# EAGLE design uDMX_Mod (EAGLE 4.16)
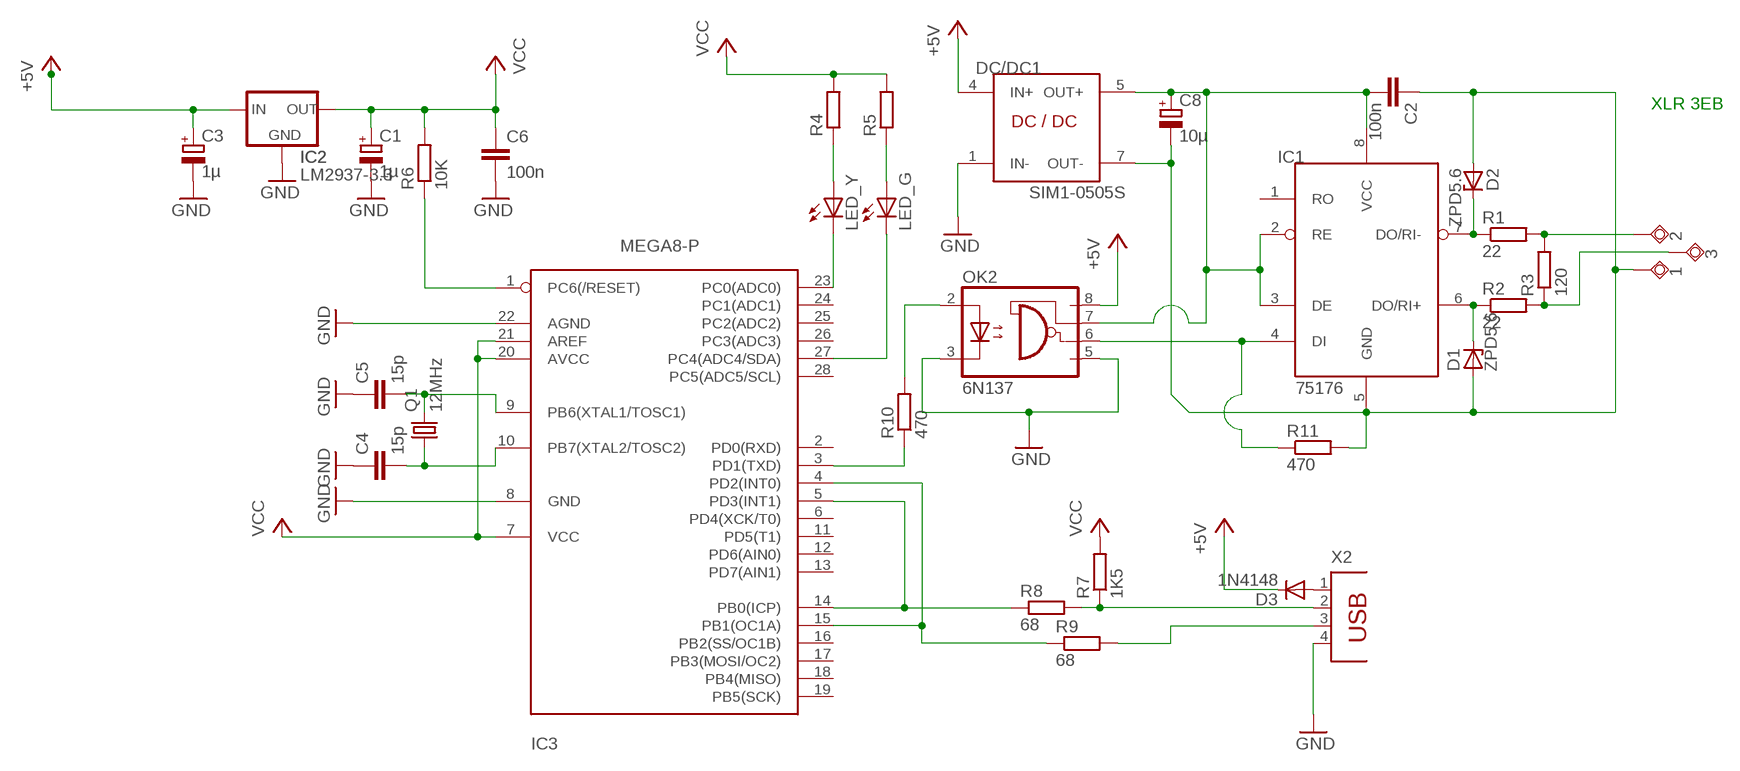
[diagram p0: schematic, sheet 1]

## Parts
1  PAD  [PAD]
2  PAD  [PAD]
3  PAD  [PAD]
C1  1µ  CPOL-EUE2.5-5  [E2,5-5]
C2  100n  C2.5/4  [C2.5-4]
C3  1µ  CPOL-EUE2.5-5  [E2,5-5]
C4  15p  C2.5/4  [C2.5-4]
C5  15p  C2.5/4  [C2.5-4]
C6  100n  C2.5/4  [C2.5-4]
C8  10µ  CPOL-EUE2.5-5  [E2,5-5]
D1  ZPD5.6  ZPD  [DO35Z10]
D2  ZPD5.6  ZPD  [DO35Z10]
D3  1N4148  [DO35-10]
DC/DC1  SIM1-0505S  [DIL08]
IC1  75176  [DIL08]
IC2  LM2937-3.3  LM2937  [TO220S]
IC3  MEGA8-P  [DIL28-3]
LED_G  LED3MM  [LED3MM]
LED_Y  LED3MM  [LED3MM]
OK2  6N137  [DIL08]
Q1  12MHz  CRYSTALHC18U-V  [HC18U-V]
R1  22  R-EU_0207/10  [0207/10]
R2  22  R-EU_0207/10  [0207/10]
R3  120  R-EU_0207/10  [0207/10]
R4  R-EU_0207/10  [0207/10]
R5  R-EU_0207/10  [0207/10]
R6  10K  R-EU_0207/10  [0207/10]
R7  1K5  R-EU_0207/10  [0207/10]
R8  68  R-EU_0207/10  [0207/10]
R9  68  R-EU_0207/10  [0207/10]
R10  470  R-EU_0207/10  [0207/10]
R11  470  R-EU_0207/10  [0207/10]
X2  PN61729  [PN61729]

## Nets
+5V: C3.+ D3.C DC/DC1.4(IN+) IC2.1(IN) OK2.8(VCC)
D-: R7.1 R8.2 X2.2
DMX2: 2.P$1(TP) R1.2 R3.2
GND: C1.- C3.- C4.1 C5.1 C6.2 DC/DC1.1(IN-) IC2.2(GND) IC3.8(GND) IC3.22(AGND) OK2.3(C) OK2.5(GND) X2.4
N$1: IC3.5(PD3(INT1)) IC3.14(PB0(ICP)) R8.1
N$2: OK2.2(A) R10.2
N$3: D2.C IC1.7(DO/RI-) R1.1
N$4: D1.C IC1.6(DO/RI+) R2.1
N$5: IC3.3(PD1(TXD)) R10.1
N$6: IC3.4(PD2(INT0)) IC3.15(PB1(OC1A)) R9.1
N$7: LED_Y.A R4.1
N$8: LED_G.A R5.1
N$9: IC3.23(PC0(ADC0)) LED_Y.K(C)
N$10: R9.2 X2.3
N$11: IC3.27(PC4(ADC4/SDA)) LED_G.K(C)
N$12: 1.P$1(TP) C2.1 C8.- D1.A D2.A DC/DC1.7(OUT-) IC1.5(GND) R11.2
N$13: 3.P$1(TP) R2.2 R3.1
N$14: D3.A X2.1
N$15: C2.2 C8.+ DC/DC1.5(OUT+) IC1.2(RE) IC1.3(DE) IC1.8(VCC) OK2.7(VE)
N$20: IC1.4(DI) OK2.6(VO) R11.1
N$37: C4.2 IC3.10(PB7(XTAL2/TOSC2)) Q1.1
N$38: C5.2 IC3.9(PB6(XTAL1/TOSC1)) Q1.2
N$47: IC3.1(PC6(/RESET)) R6.1
VCC: C1.+ C6.1 IC2.3(OUT) IC3.7(VCC) IC3.20(AVCC) IC3.21(AREF) R4.2 R5.2 R6.2 R7.2
Unconnected: IC1.1(RO) IC3.2(PD0(RXD)) IC3.6(PD4(XCK/T0)) IC3.11(PD5(T1)) IC3.12(PD6(AIN0)) IC3.13(PD7(AIN1)) IC3.16(PB2(SS/OC1B)) IC3.17(PB3(MOSI/OC2)) IC3.18(PB4(MISO)) IC3.19(PB5(SCK)) IC3.24(PC1(ADC1)) IC3.25(PC2(ADC2)) IC3.26(PC3(ADC3)) IC3.28(PC5(ADC5/SCL))

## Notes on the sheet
- XLR 3EB

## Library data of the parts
1-3 = div:PAD
C1 C3 C8 = rcl:CPOL-EU: POLARIZED CAPACITOR, European symbol
C2 C4-C6 = capacitor-wima:C: CAPACITOR
D1 D2 = diode:ZPD: Z DIODE
D3 = diode:1N4148: DIODE
DC/DC1 = Lutz:SIM1-0505S
IC1 = Lutz:75176
IC2 = Lutz:LM2937: VOLTAGE REGULATOR
IC3 = atmel:MEGA8-P: MICROCONTROLLER 8 Kbytes FLASH 1 kbytes SRAM 512 bytes EEPROM USART 4-channel 10 bit ADC 2-channel 8 bit ADC Source: avr.lbr
LED_G LED_Y = led:LED: LED
OK2 = optocoupler:6N137: MOTOROLA OPTO COUPLER
Q1 = crystal:CRYSTAL: CRYSTAL
R1-R11 = rcl:R-EU_: RESISTOR, European symbol
X2 = con-berg:PN61729: BERG USB connector

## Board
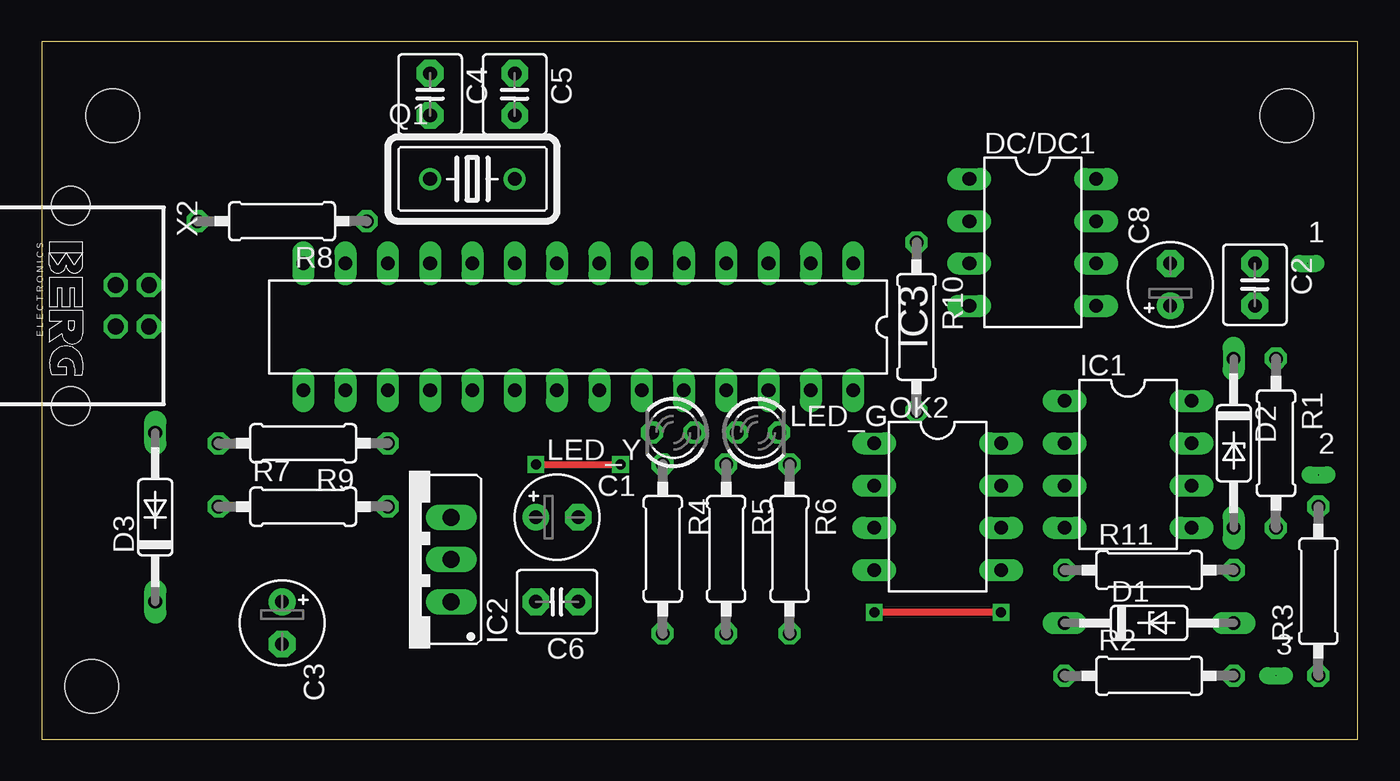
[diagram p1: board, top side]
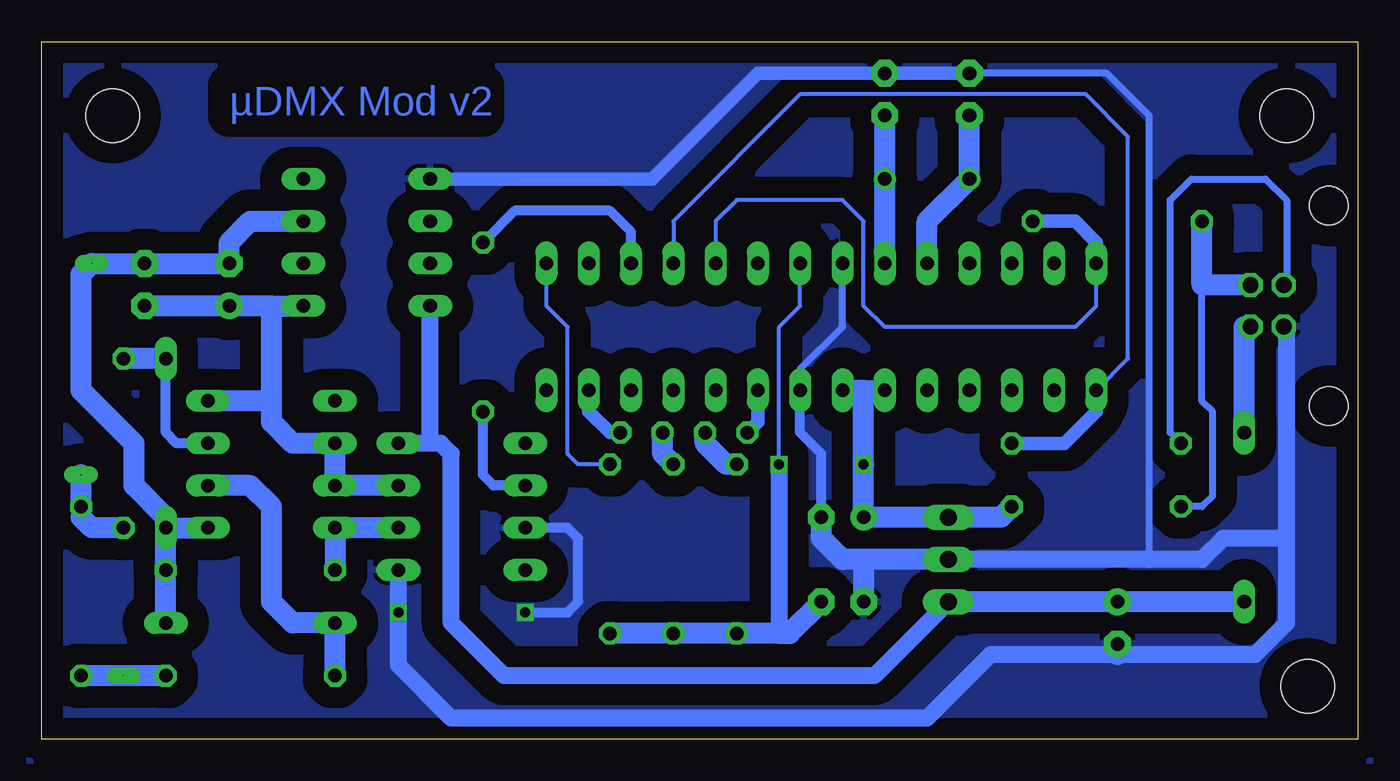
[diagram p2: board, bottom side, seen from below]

Size 79.05 x 41.9 mm. Coordinates in mm from the lower left corner, seen from the top.
Outline: 0,0 79.05,0 79.05,41.9 0,41.9 0,0
Copper layers (1*16): Top 0.035mm / dielectric 1.5mm / Bottom 0.035mm
Design rules "default": minimum track width 10mil, minimum drill 24mil, track to track 8mil, track to pad 8mil, pad to pad 8mil, via to via 8mil, smd to smd 8mil, copper to edge 40mil, drill to drill 8mil, minimum pad ring 10mil, minimum via ring 8mil, stop-mask expansion 4mil, vias tented up to drill 0mil, thermal gap 10mil
Holes 3.2 mm at 4.28,37.46 74.77,37.46 3.01,3.17

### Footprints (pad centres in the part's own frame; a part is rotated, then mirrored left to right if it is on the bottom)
PAD = drill 0.031 pad 1.016 long: P$1 0,0
E2,5-5 = drill 0.813 pad 1.6 round: + -1.27,0 | drill 0.813 pad 1.6 octagon: - 1.27,0
C2.5-4 = drill 0.813 pad 1.6 octagon: 1 -1.27,0; 2 1.27,0
DO35Z10 = drill 0.813 long: A 5.08,0; C -5.08,0
DO35-10 = drill 0.813 long: A 5.08,0; C -5.08,0
DIL08 = drill 0.813 long: 1 -3.81,-3.81; 2 -1.27,-3.81; 3 1.27,-3.81; 4 3.81,-3.81; 5 3.81,3.81; 6 1.27,3.81; 7 -1.27,3.81; 8 -3.81,3.81
TO220S = drill 1.016 long: 1 -2.54,-2.54; 2 0,-2.54; 3 2.54,-2.54
DIL28-3 = drill 0.813 long: 1 -16.51,-3.81; 2 -13.97,-3.81; 3 -11.43,-3.81; 4 -8.89,-3.81; 5 -6.35,-3.81; 6 -3.81,-3.81; 7 -1.27,-3.81; 8 1.27,-3.81; 9 3.81,-3.81; 10 6.35,-3.81; 11 8.89,-3.81; 12 11.43,-3.81; 13 13.97,-3.81; 14 16.51,-3.81; 15 16.51,3.81; 16 13.97,3.81; 17 11.43,3.81; 18 8.89,3.81; 19 6.35,3.81; 20 3.81,3.81; 21 1.27,3.81; 22 -1.27,3.81; 23 -3.81,3.81; 24 -6.35,3.81; 25 -8.89,3.81; 26 -11.43,3.81; 27 -13.97,3.81; 28 -16.51,3.81
LED3MM = drill 0.813 octagon: A -1.27,0; K 1.27,0
HC18U-V = drill 0.813 round: 1 -2.54,0; 2 2.54,0
0207/10 = drill 0.813 octagon: 1 -5.08,0; 2 5.08,0
PN61729 = drill 0.95 octagon: 1 1.25,4.71; 2 -1.25,4.71; 3 -1.25,2.71; 4 1.25,2.71 | hole 2.3: -6.02,0; 6.02,0

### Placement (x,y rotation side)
1  76.03,28.57 0 top
2  76.67,15.87 0 top
3  74.13,3.8 0 top
C1  30.95,13.33 0 top
C2  72.86,27.3 270 top
C3  14.44,6.98 270 top
C4  23.33,38.73 270 top
C5  28.41,38.73 270 top
C6  30.95,8.25 180 top
C8  67.78,27.3 90 top
D1  66.51,6.98 0 top
D2  71.59,17.77 270 top
D3  6.82,13.33 90 top
DC/DC1  59.53,29.84 270 top
IC1  65.24,16.5 270 top
IC2  22.06,10.79 90 top
IC3  32.22,24.76 180 top
LED_G  43.02,18.41 0 top
LED_Y  37.94,18.41 180 top
OK2  53.81,13.96 270 top
Q1  25.87,33.65 0 top
R1  74.13,17.77 270 top
R2  66.51,3.8 0 top
R3  76.67,8.89 90 top
R4  37.3,11.43 270 top
R5  41.11,11.43 270 top
R6  44.92,11.43 270 top
R7  15.71,13.96 0 top
R8  14.44,31.11 180 top
R9  15.71,17.77 180 top
R10  52.54,24.76 270 top
R11  66.51,10.16 0 top
X2  1.74,26.03 270 top

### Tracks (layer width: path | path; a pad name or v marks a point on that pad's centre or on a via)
+5V
  Bottom 1.016: IC2.1 29.04,3.8 51.27,3.8 54.45,6.98 54.45,17.14 55.08,17.77 55.72,17.77 | 55.72,17.77 OK2.8 | 55.72,17.77 DC/DC1.4
  Bottom 1.27: D3.C C3.+ IC2.1
D-
  Bottom 0.406: R7.1 9.36,13.96 8.72,14.6 8.72,19.68 9.36,20.31 9.36,27.3
  Bottom 1.27: X2.2 6.82,27.3 9.36,27.3 R8.2
DMX2
  Bottom 0.406: 76.67,13.33 R3.2
  Bottom 1.27: R1.2 76.03,12.7 76.67,13.33 | R3.2 2.P$1
GND  (via drill 0.6)
  Top 0.406: v57.62,7.62 v50,7.62
  Bottom 0.254: 30.95,40 C5.1 C4.1
  Bottom 0.406: IC3.8 30.95,24.76 33.49,22.22 IC3.22 | C4.1 15.07,40 12.54,37.46 12.54,10.79
  Bottom 0.61: IC3.22 33.49,18.41 32.22,17.14 C1.- | v50,7.62 47.46,7.62 46.83,8.25 46.83,12.06 47.46,12.7 OK2.3
  Bottom 0.813: DC/DC1.1 42.38,33.65 36.03,40 30.95,40 C4.1
  Bottom 1.016: OK2.5 v57.62,7.62 57.62,4.44 54.45,1.27 25.87,1.27 22.06,5.07 14.44,5.07 6.19,5.07 4.28,6.98 4.28,12.06 | 4.28,12.06 8.09,12.06 9.36,10.79 12.54,10.79 IC2.2 | X2.4 4.28,24.78 4.28,12.06
  Bottom 1.27: IC2.2 29.68,10.79 | 29.68,10.79 30.95,10.79 32.22,12.06 C1.- | 29.68,10.79 C6.2 | 14.44,5.07 C3.-
  pour Bottom (isolate 1.27): -0.8,42.54 79.84,42.54 79.84,-1.27 -0.8,-1.27
N$1
  Bottom 0.254: IC3.14 15.71,26.03 16.98,24.76 28.41,24.76 29.68,26.03 29.68,31.11 30.95,32.38 37.3,32.38 38.57,31.11 IC3.5
  Bottom 0.813: IC3.14 15.71,29.84 16.98,31.11 R8.1
N$2
  Bottom 0.61: OK2.2 51.91,15.23 52.54,15.87 R10.2
N$3
  Bottom 0.61: IC1.7 70.95,17.77 71.59,18.41 D2.C
  Bottom 1.27: D2.C R1.1
N$4
  Bottom 1.27: IC1.6 66.51,15.23 65.24,13.96 65.24,8.25 63.97,6.98 D1.C R2.1
N$5
  Bottom 0.61: R10.1 50.64,31.74 44.92,31.74 43.65,30.48 IC3.3
N$6
  Bottom 0.254: IC3.4 41.11,31.11 33.49,38.73 16.34,38.73 13.8,36.19 13.8,22.86 IC3.15
  Bottom 0.813: R9.1 17.61,17.77 15.71,19.68 IC3.15
N$7
  Bottom 1.27: R4.1 37.94,16.5 39.21,17.77 LED_Y.A
N$8
  Bottom 1.27: R5.1 41.75,17.14 LED_G.A
N$9
  Bottom 0.813: LED_Y.K 36.03,19.05 IC3.23
N$10
  Bottom 0.406: R9.2 11.26,18.41 11.26,32.38 9.99,33.65 5.55,33.65 4.28,32.38 4.28,27.3 4.3,27.28 X2.3
N$11
  Bottom 0.813: LED_G.K 44.92,18.41 46.19,19.68 IC3.27
N$12
  Bottom 1.27: D2.A R11.2 D1.A | D2.A IC1.5 | D2.A 71.59,13.33 73.5,15.23 73.5,17.77 76.67,20.95 76.67,27.94 1.P$1 C2.1 C8.- 67.78,29.84 66.51,31.11 DC/DC1.7
N$13
  Bottom 1.27: R2.2 3.P$1 R3.1
N$14
  Bottom 1.27: D3.A 6.82,24.76 X2.1
N$15
  Bottom 1.27: 65.24,26.03 DC/DC1.5 | 65.24,26.03 C8.+ C2.2 | OK2.7 IC1.3 IC1.2 63.97,17.77 65.24,19.05 65.24,20.31 | 65.24,20.31 IC1.8 | 65.24,20.31 65.24,26.03
N$20
  Bottom 1.27: OK2.6 IC1.4 R11.1
N$37
  Bottom 1.27: C4.2 Q1.1 25.87,31.11 IC3.10
N$38
  Bottom 1.27: C5.2 Q1.2 IC3.9
N$47
  Bottom 0.254: R6.1 46.83,16.5 47.46,17.14 47.46,24.76 48.73,26.03 IC3.1
VCC  (via drill 0.6)
  Top 0.406: v29.68,16.5 v34.76,16.5
  Bottom 0.254: IC3.7 33.49,26.03 34.76,24.76 v34.76,16.5
  Bottom 1.016: v34.76,16.5 34.76,6.34
  Bottom 1.27: R6.2 R5.2 R4.2 34.76,6.34 34.12,6.34 C6.1 | 29.68,20.95 IC3.21 | R7.2 21.43,13.33 IC2.3 C1.+ v29.68,16.5 29.68,20.95 | 29.68,20.95 IC3.20

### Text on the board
Bottom: µDMX Mod v2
